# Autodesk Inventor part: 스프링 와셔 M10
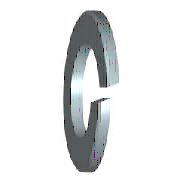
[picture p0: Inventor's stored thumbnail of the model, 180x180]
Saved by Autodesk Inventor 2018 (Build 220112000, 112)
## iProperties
IsCustomPart: 1
Created: 2012-02
Part Number: 스프링 와셔 M10
Material: 강철, 연강
Description: 스프링 와셔
Document SubType Name: Modeling
Standard: JIS B 1251
Designer: mdu-01
Standards Organization: JIS
Language: ko-KR
Size Designation: 번호 2 10
Categories: <MemberInstance><Categories><Category DisplayName="조임쇠" InternalName="e4da775c-781d-43d5-af7c-5136215cf5a6" Mnemonic="FSTN"><Category DisplayName="와셔" InternalN
Density: 1 g/cm^3
Appearance: 강철
Author: mdu-01
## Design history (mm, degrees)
sketch "스케치1"
  geometry: C1 r 9.2 at (0, 0); C2 r 5.1 at (0, 0); 1 further point
  constraints: 2 centre point, 2 coincident
  dimensions: "d0" = 10.2 diameter of C2 (= SD1); "d1" = 18.4 diameter of C1 (= SD2)
extrude "본체" new body sketch "스케치1" distance "d2" = 2.5 (= SD); taper "d3" = 0 deg
sketch "스케치2"
  geometry: L1 (0, -5.1)-(0, 5.1) reference; L2 (2.5, 9.2)-(2.5, -9.2) reference; L3 (-1.2, 0)-(7.2, 0) reference; L4 (0, -0.5)-(2.5, 0.41); L5 (0, 0.5)-(2.5, 1.41)
  constraints: 4 end point, 4 point on line, 1 parallel
  dimensions: "d4" = 0.5 distance from line of L3 L4.start (= 0.2 x SD); "d5" = 0.5 distance from line of L3 L5.start (= 0.2 x SD); "d6" = 70 deg angle of L2 L4 (= FAWI)
extrude "절단부" cut sketch "스케치2" stored distance "d7" = 2.5 (= SD); taper "d8" = 0 deg
workaxis "Work Axis1"
workplane "Work Plane1"
body "Solid1"
other parameters: "SD1" = 10.2 [user parameter; used in 1 equation term], "SD2" = 18.4 [user parameter; used in 1 equation term], "SD" = 2.5 [user parameter; used in 4 equation terms], "FAWI" = 70 deg [user parameter; used in 1 equation term], "d9" = 0, "d10" = 0, "d11" = 0, "d12" = 0, "SDI" = 3.7 [user parameter]
